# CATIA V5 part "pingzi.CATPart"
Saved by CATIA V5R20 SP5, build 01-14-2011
Part number: 可乐饮料瓶
Material "Bright Plastic": density 1200 kg/m3, Young's modulus 2.2e+09 Pa, Poisson ratio 0.38, thermal expansion 6.84e-05 1/K
Bounding box of the stored display mesh (mm): x 0 to 50, y -50 to 0, z 0 to 110
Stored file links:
  D:\三维工程制图——产品三维建模技术 (F)\第3章-产品的零件建模\例3-5 饮料瓶的特征造型\可乐饮料瓶源文件从装配文件打开\pingzi.CATPart
  F:\CATIA\Part2.CATPart
  e:\Program Files\Dassault Systemes\B17\intel_a\startup\materials\Simplified_Chinese\Catalog.CATMaterial
  C:\Program Files\Dassault Systemes\B20\intel_a\startup\materials\DS_star.jpg
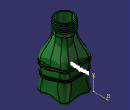
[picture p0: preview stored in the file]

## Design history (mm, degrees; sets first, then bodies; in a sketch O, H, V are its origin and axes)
Set1 "几何图形集.1"
  Point1: type OnCurve, Support edge [face of Pad1 from Sketch11.L1 | face of Pad1 from Sketch11.L2], Ratio 0.5
  Point2: type OnCurve, Support edge [face of Pad1 from Sketch11.L2 | face of Pad1 from Sketch11.L3], Ratio 0.5
  Point3: type OnCurve, Support edge [face of Pad1 from Sketch11.L3 | face of Pad1 from Sketch11.L4], Ratio 0.5
  Point4: type OnCurve, Support edge [face of Pad1 from Sketch11.L4 | face of Pad1 from Sketch11.L1], Ratio 0.5
  Point5: type OnCurve, Support edge [start face of Pad1 | face of Pad1 from Sketch11.L2], Ratio 0.5
  Point6: type OnCurve, Support edge [start face of Pad1 | face of Pad1 from Sketch11.L3], Ratio 0.5
  Point7: type OnCurve, Support edge [start face of Pad1 | face of Pad1 from Sketch11.L4], Ratio 0.5
  Point8: type OnCurve, Support edge [start face of Pad1 | face of Pad1 from Sketch11.L1], Ratio 0.5
  Plane1: type Offset, RefPlane end face of Pad1, Offset 40, reversed
  Point9: type OnCurve, Support edge [face of Pad1 from Sketch11.L1 | end face of Pad1], Ratio 0.5
  Sketch1 "草图.3" on start face of Pad2, origin (0, 0, 90), H (1, 0, 0), V (0, -1, 0)
    point P1 (25, 10)
    reference projected circle E1 centre (25, 25) radius 15 from edge [face of Pad2 from Sketch12.A1 | start face of Pad2]
    distance P1 V = 25
    coincidence: P1 E1
  Boundary1: Boundary {extract ExtractElem end face of Pad1}
  Boundary2: Boundary {extract ExtractElem start face of Pad2}
  Sketch2 "草图.4" on face of Pad1 from Sketch11.L2, origin (50, 0, 0), H (0, 1, 0), V (0, 0, 1)
    spline S1 through (-55, 35) (-30, 30) (-15, 35) (15, 30)
    point P1 (15, 30)
    point P2 (-15, 35)
    point P3 (-30, 30)
    point P4 (-55, 35)
    distance P1 V = 15
    distance P2 V = 15
    distance P1 H = 30
    distance P3 H = 30
    distance P3 V = 30
    distance P2 H = 35
    distance P4 H = 35
    distance P4 V = 55
  Extrude1: Element1 Sketch2, Lim1 50, Lim2 0
  MultiSel1
  Join1: Elements ({intersect ToIntersect1 Extrude1, ToIntersect2 {extract ExtractElem face of Fillet1}}; {intersect ToIntersect1 Extrude1, ToIntersect2 {extract ExtractElem face of Pad1 from Sketch11.L3}}; {intersect ToIntersect1 Extrude1, ToIntersect2 {extract ExtractElem face of Fillet1}}; {intersect ToIntersect1 Extrude1, ToIntersect2 {extract ExtractElem face of Pad1 from Sketch11.L2}}; {intersect ToIntersect1 Extrude1, ToIntersect2 {extract ExtractElem face of Fillet1}}; {intersect ToIntersect1 Extrude1, ToIntersect2 {extract ExtractElem face of Pad1 from Sketch11.L1}}; {intersect ToIntersect1 Extrude1, ToIntersect2 {extract ExtractElem face of Fillet1}}; {intersect ToIntersect1 Extrude1, ToIntersect2 {extract ExtractElem face of Pad1 from Sketch11.L4}})
  Plane2: type Offset, RefPlane yz-plane, Offset 25
  Sketch3 on Plane2, origin (25, 0, 0), H (0, 1, 0), V (0, 0, 1)
    circle A1 centre (1, 36.455) radius 2
    point P1 (1, 36.455)
    reference projected point E1 (0, 36.455) from vertex [face of MultiSel1 | face of MultiSel1]
    reference projected point E2 (0, 36.455) from vertex [face of MultiSel1 | face of MultiSel1]
    radius A1 = 2
    distance P1 E1 H = 1
    distance P1 E2 V = 0
  Translate1: ToTransfor Extrude1, Direction (0, 0, 1), Length 15
  MultiSel2
  Join2: Elements ({intersect ToIntersect1 Translate1, ToIntersect2 {extract ExtractElem face of Loft1}}; {intersect ToIntersect1 Translate1, ToIntersect2 {extract ExtractElem face of Loft1}}; {intersect ToIntersect1 Translate1, ToIntersect2 {extract ExtractElem face of Pad1 from Sketch11.L2}}; {intersect ToIntersect1 Translate1, ToIntersect2 {extract ExtractElem face of Fillet1}}; {intersect ToIntersect1 Translate1, ToIntersect2 {extract ExtractElem face of Pad1 from Sketch11.L3}}; {intersect ToIntersect1 Translate1, ToIntersect2 {extract ExtractElem face of Fillet1}}; {intersect ToIntersect1 Translate1, ToIntersect2 {extract ExtractElem face of Pad1 from Sketch11.L4}}; {intersect ToIntersect1 Translate1, ToIntersect2 {extract ExtractElem face of Loft1}}; {intersect ToIntersect1 Translate1, ToIntersect2 {extract ExtractElem face of Loft1}}; {intersect ToIntersect1 Translate1, ToIntersect2 {extract ExtractElem face of Loft1}})
  Sketch4 on Plane2, origin (25, 0, 0), H (0, 1, 0), V (0, 0, 1)
    circle A1 centre (-51, 47.0591) radius 2
    point P1 (-51, 47.0591)
    reference projected point E1 (-50, 47.0591) from vertex [face of MultiSel2 | face of MultiSel2]
    reference projected point E2 (-50, 47.0591) from vertex [face of MultiSel2 | face of MultiSel2]
    distance P1 E1 H = 1
    radius A1 = 2
    distance E2 P1 V = 0
  Point10: (25, -10, 94)
  Point11: (25, -25, 110)
  Line1: type PtDir, RefPoint Point11, Direction (0, 0, 1), Start 0, End 20
  Helix1: Direction Line1, RefPoint Point10, Pitch 3, Height 15, TaperAngle 0
  Line2: type PtDir, RefPoint Point10, Direction (0, 1, 0), Start 0, End 2
  Point12: type OnCurve, Support Helix1, Length 2
  Connect1: Curve1 Helix1, Point1 Point12, Tension1 1, Curve2 Line2, Point2 vertex of Line2, Tension2 1
  Line3: type PtDir, RefPoint vertex of Helix1, Direction (0, 1, 0), Start 0, End 2
  Point13: type OnCurve, Support Connect1, Length 2
  Connect2: Curve1 Line3, Point1 vertex of Line3, Tension1 1, Curve2 Connect1, Point2 Point13, Tension2 1
  Circle1: type CtrRad, Start 0, End 180, Center vertex of Connect1, Support {plane type OffsetPt, RefPlane zx-plane, RefPoint vertex of Connect1}, Radius 1, FirstDirection (-1, 0, 0)
Set2 "几何图形集.2"
  Sketch5 on xy-plane, origin (0, 0, 0), H (1, 0, 0), V (0, 1, 0)
    line L1 (48, -48) -> (2, -48)
    line L2 (48, -2) -> (48, -48)
    line L3 (2, -48) -> (2, -2)
    point P1 (2, -2)
    line L4 (2, -2) -> (48, -2)
    distance L2 L3 = 46
    distance L4 L1 = 46
    distance P1 H = 2
    distance P1 V = 2
    horizontal: L1 H, L4 H
    vertical: L2 V, L3 V
    perpendicularity: L4 L2
  Point14: type OnCurve, Support edge [face of Pad3 from Sketch5.L3 | face of Pad3 from Sketch5.L4], Ratio 0.5
  Point15: type OnCurve, Support edge [face of Pad3 from Sketch5.L1 | face of Pad3 from Sketch5.L3], Ratio 0.5
  Point16: type OnCurve, Support edge [face of Pad3 from Sketch5.L4 | face of Pad3 from Sketch5.L2], Ratio 0.5
  Point17: type OnCurve, Support edge [face of Pad3 from Sketch5.L2 | face of Pad3 from Sketch5.L1], Ratio 0.5
  Point18: type OnCurve, Support edge [start face of Pad3 | face of Pad3 from Sketch5.L3], Ratio 0.5
  Point19: type OnCurve, Support edge [start face of Pad3 | face of Pad3 from Sketch5.L4], Ratio 0.5
  Point20: type OnCurve, Support edge [start face of Pad3 | face of Pad3 from Sketch5.L2], Ratio 0.5
  Point21: type OnCurve, Support edge [start face of Pad3 | face of Pad3 from Sketch5.L1], Ratio 0.5
  Sketch6 on Plane1, origin (0, 0, 90), H (1, 0, 0), V (0, -1, 0)
    circle A1 centre (25, 25) radius 13
    point P1 (25, 25)
    radius A1 = 13
    distance P1 H = 25
    distance V P1 = 25
  Point22: type OnCurve, Support edge [face of Pad3 from Sketch5.L4 | end face of Pad3], Ratio 0.5
  Sketch7 on start face of Pad4, origin (0, 0, 90), H (1, 0, 0), V (0, -1, 0)
    point P1 (25, 12)
    reference projected circle E1 centre (25, 25) radius 13 from edge [face of Pad4 from Sketch6.A1 | start face of Pad4]
    distance P1 V = 25
    coincidence: P1 E1
  Boundary3: Boundary {extract ExtractElem start face of Pad4}
  Boundary4: Boundary {extract ExtractElem end face of Pad3}
  MultiSel3
  Join3: Elements ({intersect ToIntersect1 Extrude1, ToIntersect2 {extract ExtractElem face of Fillet4}}; {intersect ToIntersect1 Extrude1, ToIntersect2 {extract ExtractElem face of Pad3 from Sketch5.L3}}; {intersect ToIntersect1 Extrude1, ToIntersect2 {extract ExtractElem face of Fillet4}}; {intersect ToIntersect1 Extrude1, ToIntersect2 {extract ExtractElem face of Pad3 from Sketch5.L4}}; {intersect ToIntersect1 Extrude1, ToIntersect2 {extract ExtractElem face of Fillet4}}; {intersect ToIntersect1 Extrude1, ToIntersect2 {extract ExtractElem face of Pad3 from Sketch5.L2}}; {intersect ToIntersect1 Extrude1, ToIntersect2 {extract ExtractElem face of Fillet4}}; {intersect ToIntersect1 Extrude1, ToIntersect2 {extract ExtractElem face of Pad3 from Sketch5.L1}})
  MultiSel4
  Join4: Elements ({intersect ToIntersect1 Translate1, ToIntersect2 {extract ExtractElem face of Pad3 from Sketch5.L2}}; {intersect ToIntersect1 Translate1, ToIntersect2 {extract ExtractElem face of Loft2}}; {intersect ToIntersect1 Translate1, ToIntersect2 {extract ExtractElem face of Loft2}}; {intersect ToIntersect1 Translate1, ToIntersect2 {extract ExtractElem face of Loft2}}; {intersect ToIntersect1 Translate1, ToIntersect2 {extract ExtractElem face of Loft2}}; {intersect ToIntersect1 Translate1, ToIntersect2 {extract ExtractElem face of Pad3 from Sketch5.L3}}; {intersect ToIntersect1 Translate1, ToIntersect2 {extract ExtractElem face of Fillet4}}; {intersect ToIntersect1 Translate1, ToIntersect2 {extract ExtractElem face of Pad3 from Sketch5.L1}}; {intersect ToIntersect1 Translate1, ToIntersect2 {extract ExtractElem face of Fillet4}}; {intersect ToIntersect1 Translate1, ToIntersect2 {extract ExtractElem face of Loft2}})
  Sketch8 on Plane2, origin (25, 0, 0), H (0, 1, 0), V (0, 0, 1)
    circle A1 centre (-1, 36.6906) radius 2
    point P1 (-1, 36.6906)
    reference projected point E1 (-2, 36.6906) from vertex [face of MultiSel3 | face of MultiSel3]
    reference projected point E2 (-2, 36.6906) from vertex [face of MultiSel3 | face of MultiSel3]
    radius A1 = 2
    distance P1 E1 H = 1
    distance P1 E2 V = 0
  Sketch9 on Plane2, origin (25, 0, 0), H (0, 1, 0), V (0, 0, 1)
    circle A1 centre (-49, 46.1561) radius 2
    point P1 (-49, 46.1561)
    reference projected point E1 (-48, 46.1561) from vertex [face of MultiSel4 | face of MultiSel4]
    reference projected point E2 (-48, 46.1561) from vertex [face of MultiSel4 | face of MultiSel4]
    radius A1 = 2
    distance P1 E1 H = 1
    distance P1 E2 V = 0
  Sketch10 on face of Pad1 from Sketch11.L3, origin (0, -50, 0), H (1, 0, 0), V (0, 0, 1)
    polyline C1
    polyline C2
    polyline C3
    polyline C4
    polyline C5
    polyline C6
    polyline C7
    polyline C8
    polyline C9
    polyline C10
    polyline C11
    polyline C12
    polyline C13
    polyline C14
Body1 (main body), material "Bright Plastic"
  Sketch11 on xy-plane, origin (0, 0, 0), H (1, 0, 0), V (0, 1, 0)
    line L1 (0, 0) -> (50, 0)
    line L2 (50, 0) -> (50, -50)
    line L3 (50, -50) -> (0, -50)
    line L4 (0, -50) -> (0, 0)
    length L2 = 50
    length L3 = 50
    horizontal: L1 H, L3 H
    vertical: L2 V, L4 V
  Pad1: profile Sketch11, direction (0, 0, 1), length 50
  Fillet1: on edge [face of Pad1 from Sketch11.L1 | face of Pad1 from Sketch11.L2]; edge [face of Pad1 from Sketch11.L2 | face of Pad1 from Sketch11.L3]; edge [face of Pad1 from Sketch11.L3 | face of Pad1 from Sketch11.L4]; edge [face of Pad1 from Sketch11.L4 | face of Pad1 from Sketch11.L1]
  Fillet2: on edge [start face of Pad1 | face of Fillet1] (x4); edge [start face of Pad1 | face of Pad1 from Sketch11.L2]; edge [start face of Pad1 | face of Pad1 from Sketch11.L3]; edge [start face of Pad1 | face of Pad1 from Sketch11.L4]; edge [start face of Pad1 | face of Pad1 from Sketch11.L1]
  Sketch12 on Plane1, origin (0, 0, 90), H (1, 0, 0), V (0, -1, 0)
    circle A1 centre (25, 25) radius 15
    point P1 (25, 25)
    radius A1 = 15
    distance P1 H = 25
    distance P1 V = 25
  Pad2: profile Sketch12, direction (0, 0, 1), length 20
  Loft1: solid, Sections (Boundary1; Boundary2), StartFace end face of Pad1, EndFace start face of Pad2
  Slot1: profile Sketch3, centre curve Join1
  Slot2: profile Sketch4, centre curve Join2
  Fillet3: radius 1, on edge [face of Fillet1 | face of Slot1] (x3); edge [face of Slot1 | face of Fillet1] (x4); edge [face of Fillet1 | face of Slot2] (x3); edge [face of Loft1 | face of Slot2] (x2); edge [face of Slot2 | face of Fillet1] (x3); edge [face of Slot2 | face of Pad1 from Sketch11.L1]; edge [face of Pad1 from Sketch11.L4 | face of Slot2]; edge [face of Pad1 from Sketch11.L3 | face of Slot2]; edge [face of Slot2 | face of Pad1 from Sketch11.L3]; edge [face of Slot2 | face of Loft1]
  Rib1: profile Circle1, centre curve Connect2
  Body2
    Pad3: profile Sketch5, direction (0, 0, 1), length 50, opposite side length -2
    Fillet4: on edge [face of Pad3 from Sketch5.L4 | face of Pad3 from Sketch5.L2]; edge [face of Pad3 from Sketch5.L2 | face of Pad3 from Sketch5.L1]; edge [face of Pad3 from Sketch5.L3 | face of Pad3 from Sketch5.L4]; edge [face of Pad3 from Sketch5.L1 | face of Pad3 from Sketch5.L3]
    Fillet5: on edge [start face of Pad3 | face of Fillet4] (x4); edge [start face of Pad3 | face of Pad3 from Sketch5.L4]; edge [start face of Pad3 | face of Pad3 from Sketch5.L2]; edge [start face of Pad3 | face of Pad3 from Sketch5.L1]; edge [start face of Pad3 | face of Pad3 from Sketch5.L3]
    Pad4: profile Sketch6, direction (0, 0, 1), length 20
    Loft2: solid, Sections (Boundary3; Boundary4), StartFace start face of Pad4, EndFace end face of Pad3
    Slot3: profile Sketch8, centre curve Join3
    Slot4: profile Sketch9, centre curve Join4
  Remove1: tool Body2
Body3
  Sketch13 on yz-plane, origin (0, 0, 0), H (0, 1, 0), V (0, 0, 1)
    polyline C1
    polyline C2
    polyline C3
    polyline C4
    polyline C5
    polyline C6
    polyline C7
    polyline C8
    polyline C9
    polyline C10
    polyline C11
    polyline C12
    polyline C13
    polyline C14
    polyline C15
    polyline C16
    polyline C17
    polyline C18
    polyline C19
    polyline C20
    polyline C21
    polyline C22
